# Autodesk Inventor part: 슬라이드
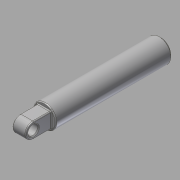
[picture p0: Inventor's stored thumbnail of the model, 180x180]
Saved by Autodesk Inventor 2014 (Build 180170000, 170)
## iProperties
Created: 2016-02
Part Number: 슬라이드
Material: 강철, 연강
Document SubType Name: Modeling
Designer: test
Density: 1 g/cm^3
Appearance: 강철
Author: test
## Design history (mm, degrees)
sketch "스케치2"
  geometry: C1 r 6 at (0, 0); 1 further point
  constraints: 1 centre point, 1 coincident
  dimensions: "d0" = 12 diameter of C1
extrude "돌출1" new body sketch "스케치2" distance "d1" = 60; taper "d2" = 0 deg
hole "구멍1" diameter "d5" = 5.917; stored, may be unused: countersink angle "d9" = 90 deg, drill point angle "d11" = 118 deg; dims "d3" = 10, "d4" = 10, "d6" = 10, "d7" = 4, "d8" = 2, "d10" = 12
chamfer "모따기1" distance "d12" = 1; stored, may be unused: second distance "d13" = 2, angle "d14" = 45 deg
sketch "스케치3"
  geometry: L1 (0, 6)-(0, -6) reference; L2 (0, 4)-(-9, 4); L3 (-9, -4)-(0, -4); L4 (0, -4)-(0, 4); C1 r 2.5 at (-9, 0); A1 r 4 centre (-9, 0) between (-9, 4) and (-9, -4); 2 further points
  constraints: 6 end point, 2 centre point, 2 point on circle, 2 tangent, 1 coincident, 1 horizontal, 1 horizontal alignment, 1 midpoint, 1 parallel, 1 point on line, 1 vertical
  dimensions: "d15" = 13 dimension on A1 L1; "d16" = 8 distance between parallel lines of L3 L2; "d17" = 5 diameter of C1
extrude "돌출2" join sketch "스케치3" stored distance "d18" = 7; taper "d19" = 0 deg
chamfer "모따기2" distance "d20" = 0.5; stored, may be unused: second distance "d21" = 2, angle "d22" = 45 deg
fillet "모깎기1" dims "d23" = 0.5
fillet "모깎기2" dims "d24" = 0.5
fillet "모깎기3" dims "d25" = 0.5
node "솔리드1"
